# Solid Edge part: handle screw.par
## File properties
Accuracy: 0.99
Title: Handle Screw
Author: Robert a Rhodes jr
Template: Normal.par
Last saved by: TIET
Revision: 11
Application: Solid Edge
Material: aluminum
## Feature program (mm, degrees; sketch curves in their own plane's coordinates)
sketch for "unnamed Protrusion 1" plane through (0, 0, 0) normal (0, -1, 0) x-axis (1, 0, 0)
  circle centre (0, 0) radius 7.5
extrude "unnamed Protrusion 1" add finite 14 along +normal
sketch for "Hole_1" plane through (0, -14, 0) normal (0, -1, 0) x-axis (1, 0, 0)
  hole centre (0, 0) bore radius 4
hole "Hole_1" diameter 8 finite  VBottomAngle = 120 deg
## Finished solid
Body 1: solid body, 5 faces, 4 edges, 1 vertex.
  Faces by surface: cylinder 2, plane 2, cone 1
  Edges by curve: circle 4
Bounding box of the edges (mm): 15.000 x 14.000 x 15.000, from (-7.5, -14, -7.5) to (7.5, 0, 7.5).
Cylindrical faces by radius (mm): R4 x1, R7.5 x1
Conical faces (half-angle, radius in mm at the cone's reference point): 60 deg R4 x1
Planar faces by outward normal: +y 1, -y 1
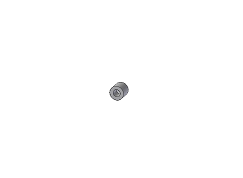
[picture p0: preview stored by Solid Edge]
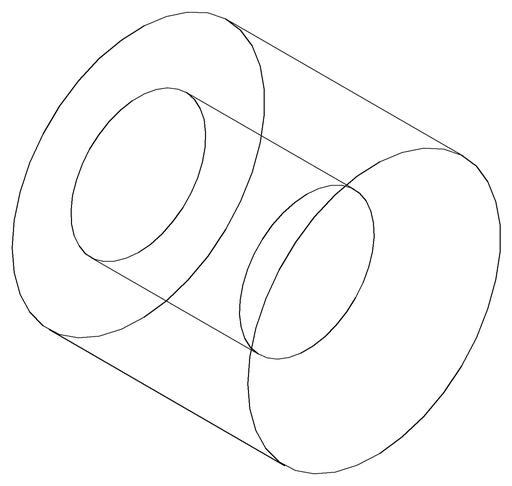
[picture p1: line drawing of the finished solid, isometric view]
